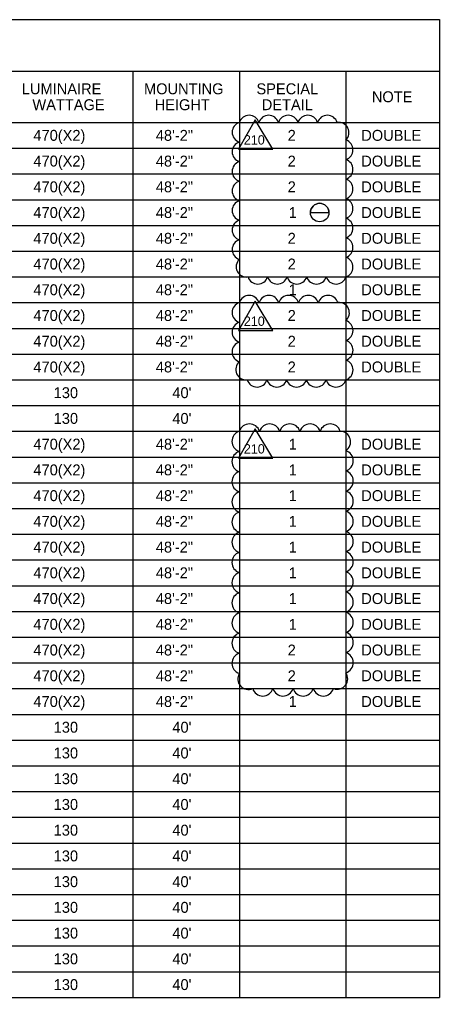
# Model space of a CAD drawing. Extents: x -816.7 to -800.7, y -2197.9 to -2187.9.
# Drawn here: x -811.23 to -808.54, y -2194.13 to -2187.86 of the extents above; entities that cross this region are included whole.
import ezdxf

# ---------------------------------------------------------------- set-up
doc = ezdxf.new("R2010")
doc.units = 0
for name, color, linetype in [('ScratchEle_dp', 7, 'Continuous'), ('SumBoxBorder_dp', 7, 'Continuous'), ('SumBoxLines_dp', 7, 'Continuous'), ('SumBoxLinesMin_dp', 7, 'Continuous'), ('TextLabel', 7, 'Continuous')]:
    doc.layers.add(name, color=color, linetype=linetype)

msp = doc.modelspace()

# ---------------------------------------------------------------- linework, layer by layer
at = {"layer": 'ScratchEle_dp'}
for points in [[(-809.7225, -2188.4998), (-809.8303, -2188.6879), (-809.6096, -2188.6879)], [(-809.7225, -2189.6621), (-809.8303, -2189.8502), (-809.6096, -2189.8502)], [(-809.7225, -2190.4807), (-809.8303, -2190.6688), (-809.6096, -2190.6688)]]:
    msp.add_lwpolyline(points, close=True, dxfattribs=at)
for centre, radius, start, end in [((-809.7621, -2188.536), 0.0657, 17.5, 162.5), ((-809.6368, -2188.536), 0.0657, 17.5, 162.5), ((-809.5114, -2188.536), 0.0657, 17.5, 162.5), ((-809.386, -2188.536), 0.0657, 17.5, 162.5), ((-809.2606, -2188.536), 0.0657, 17.5, 162.5), ((-809.8051, -2188.5789), 0.0657, 107.5, 252.5), ((-809.1878, -2188.5811), 0.0657, 313.82811, 98.82811), ((-809.8051, -2188.7043), 0.0657, 107.5, 252.5), ((-809.1621, -2188.6912), 0.0657, 287.5, 72.5), ((-809.8051, -2188.8297), 0.0657, 107.5, 252.5), ((-809.1621, -2188.8166), 0.0657, 287.5, 72.5), ((-809.8051, -2188.9551), 0.0657, 107.5, 252.5), ((-809.1621, -2188.942), 0.0657, 287.5, 72.5), ((-809.8051, -2189.0804), 0.0657, 107.5, 252.5), ((-809.1621, -2189.0674), 0.0657, 287.5, 72.5), ((-809.8051, -2189.2058), 0.0657, 107.5, 252.5), ((-809.1621, -2189.1927), 0.0657, 287.5, 72.5), ((-809.8051, -2189.3312), 0.0657, 107.5, 252.5), ((-809.1621, -2189.3181), 0.0657, 287.5, 72.5), ((-809.7794, -2189.4413), 0.0657, 133.82811, 278.82811), ((-809.1621, -2189.4435), 0.0657, 287.5, 72.5), ((-809.7066, -2189.4864), 0.0657, 197.5, 342.5), ((-809.5812, -2189.4864), 0.0657, 197.5, 342.5), ((-809.4558, -2189.4864), 0.0657, 197.5, 342.5), ((-809.3304, -2189.4864), 0.0657, 197.5, 342.5), ((-809.205, -2189.4864), 0.0657, 197.5, 342.5), ((-809.8049, -2189.7344), 0.0663, 107.5, 252.5), ((-809.7616, -2189.6911), 0.0663, 17.5, 162.5), ((-809.6352, -2189.6911), 0.0663, 17.5, 162.5), ((-809.5088, -2189.6911), 0.0663, 17.5, 162.5), ((-809.3824, -2189.6911), 0.0663, 17.5, 162.5), ((-809.256, -2189.6911), 0.0663, 17.5, 162.5), ((-809.1858, -2189.737), 0.0662, 311.04336, 96.04336), ((-809.1623, -2189.8502), 0.0663, 287.5, 72.5), ((-809.8049, -2189.8608), 0.0663, 107.5, 252.5), ((-809.1623, -2189.9766), 0.0663, 287.5, 72.5), ((-809.8049, -2189.9872), 0.0663, 107.5, 252.5), ((-809.1623, -2190.103), 0.0663, 287.5, 72.5), ((-809.7814, -2190.1004), 0.0662, 131.04336, 276.04336), ((-809.7112, -2190.1463), 0.0663, 197.5, 342.5), ((-809.5848, -2190.1463), 0.0663, 197.5, 342.5), ((-809.4584, -2190.1463), 0.0663, 197.5, 342.5), ((-809.332, -2190.1463), 0.0663, 197.5, 342.5), ((-809.2055, -2190.1463), 0.0663, 197.5, 342.5), ((-809.7601, -2190.5166), 0.0678, 17.5, 162.5), ((-809.6307, -2190.5166), 0.0678, 17.5, 162.5), ((-809.5013, -2190.5166), 0.0678, 17.5, 162.5), ((-809.3719, -2190.5166), 0.0678, 17.5, 162.5), ((-809.2425, -2190.5166), 0.0678, 17.5, 162.5), ((-809.8044, -2190.5609), 0.0678, 107.5, 252.5), ((-809.1797, -2190.564), 0.0678, 303.41343, 88.41343), ((-809.8044, -2190.6903), 0.0678, 107.5, 252.5), ((-809.1627, -2190.6853), 0.0678, 287.5, 72.5), ((-809.8044, -2190.8197), 0.0678, 107.5, 252.5), ((-809.1627, -2190.8147), 0.0678, 287.5, 72.5), ((-809.8044, -2190.9491), 0.0678, 107.5, 252.5), ((-809.1627, -2190.9441), 0.0678, 287.5, 72.5), ((-809.8044, -2191.0785), 0.0678, 107.5, 252.5), ((-809.1627, -2191.0735), 0.0678, 287.5, 72.5), ((-809.8044, -2191.2079), 0.0678, 107.5, 252.5), ((-809.1627, -2191.2029), 0.0678, 287.5, 72.5), ((-809.8044, -2191.3374), 0.0678, 107.5, 252.5), ((-809.1627, -2191.3323), 0.0678, 287.5, 72.5), ((-809.8044, -2191.4668), 0.0678, 107.5, 252.5), ((-809.1627, -2191.4617), 0.0678, 287.5, 72.5), ((-809.8044, -2191.5962), 0.0678, 107.5, 252.5), ((-809.1627, -2191.5912), 0.0678, 287.5, 72.5), ((-809.8044, -2191.7256), 0.0678, 107.5, 252.5), ((-809.1627, -2191.7206), 0.0678, 287.5, 72.5), ((-809.8044, -2191.855), 0.0678, 107.5, 252.5), ((-809.1627, -2191.85), 0.0678, 287.5, 72.5), ((-809.8044, -2191.9844), 0.0678, 107.5, 252.5), ((-809.1627, -2191.9794), 0.0678, 287.5, 72.5), ((-809.7668, -2192.0842), 0.0678, 148.8508, 293.8508), ((-809.1981, -2192.0826), 0.0678, 249.63724, 34.63724), ((-809.6747, -2192.1258), 0.0678, 197.5, 342.5), ((-809.5453, -2192.1258), 0.0678, 197.5, 342.5), ((-809.4159, -2192.1258), 0.0678, 197.5, 342.5), ((-809.2864, -2192.1258), 0.0678, 197.5, 342.5)]:
    msp.add_arc(centre, radius, start, end, dxfattribs=at)
at = {"layer": 'SumBoxBorder_dp'}
for p, q in [((-815.9673, -2187.8562), (-808.5423, -2187.8562)), ((-808.5423, -2187.8562), (-808.5423, -2194.1262)), ((-808.5423, -2187.8562), (-808.5423, -2194.1262)), ((-815.9673, -2188.1862), (-808.5423, -2188.1862)), ((-815.9673, -2188.1862), (-808.5423, -2188.1862)), ((-815.9673, -2194.1262), (-808.5423, -2194.1262))]:
    msp.add_line(p, q, dxfattribs=at)
at = {"layer": 'SumBoxLines_dp'}
for p, q in [((-810.5073, -2188.1862), (-810.5073, -2194.1262)), ((-810.5073, -2188.1862), (-810.5073, -2194.1262)), ((-809.8248, -2188.1862), (-809.8248, -2194.1262)), ((-809.8248, -2188.1862), (-809.8248, -2192.3112)), ((-809.1423, -2188.1862), (-809.1423, -2194.1262)), ((-815.9673, -2188.5162), (-808.5423, -2188.5162)), ((-809.8248, -2192.4762), (-809.8248, -2194.1262))]:
    msp.add_line(p, q, dxfattribs=at)
at = {"layer": 'SumBoxLinesMin_dp'}
for p, q in [((-815.9673, -2188.5162), (-808.5423, -2188.5162)), ((-815.9673, -2188.6812), (-808.5423, -2188.6812)), ((-815.9673, -2188.6812), (-808.5423, -2188.6812)), ((-815.9673, -2188.8462), (-808.5423, -2188.8462)), ((-815.9673, -2188.8462), (-808.5423, -2188.8462)), ((-815.9673, -2189.0112), (-808.5423, -2189.0112)), ((-815.9673, -2189.0112), (-808.5423, -2189.0112)), ((-815.9673, -2189.1762), (-808.5423, -2189.1762)), ((-815.9673, -2189.1762), (-808.5423, -2189.1762)), ((-815.9673, -2189.3412), (-808.5423, -2189.3412)), ((-815.9673, -2189.3412), (-808.5423, -2189.3412)), ((-815.9673, -2189.5062), (-808.5423, -2189.5062)), ((-815.9673, -2189.5062), (-808.5423, -2189.5062)), ((-815.9673, -2189.6712), (-808.5423, -2189.6712)), ((-815.9673, -2189.6712), (-808.5423, -2189.6712)), ((-815.9673, -2189.8362), (-808.5423, -2189.8362)), ((-815.9673, -2189.8362), (-808.5423, -2189.8362)), ((-815.9673, -2190.0012), (-808.5423, -2190.0012)), ((-815.9673, -2190.0012), (-808.5423, -2190.0012)), ((-815.9673, -2190.1662), (-808.5423, -2190.1662)), ((-815.9673, -2190.1662), (-808.5423, -2190.1662)), ((-815.9673, -2190.3312), (-808.5423, -2190.3312)), ((-815.9673, -2190.3312), (-808.5423, -2190.3312)), ((-815.9673, -2190.4962), (-808.5423, -2190.4962)), ((-815.9673, -2190.4962), (-808.5423, -2190.4962)), ((-815.9673, -2190.6612), (-808.5423, -2190.6612)), ((-815.9673, -2190.6612), (-808.5423, -2190.6612)), ((-815.9673, -2190.8262), (-808.5423, -2190.8262)), ((-815.9673, -2190.8262), (-808.5423, -2190.8262)), ((-815.9673, -2190.9912), (-808.5423, -2190.9912)), ((-815.9673, -2190.9912), (-808.5423, -2190.9912)), ((-815.9673, -2191.1562), (-808.5423, -2191.1562)), ((-815.9673, -2191.1562), (-808.5423, -2191.1562)), ((-815.9673, -2191.3212), (-808.5423, -2191.3212)), ((-815.9673, -2191.3212), (-808.5423, -2191.3212)), ((-815.9673, -2191.4862), (-808.5423, -2191.4862)), ((-815.9673, -2191.4862), (-808.5423, -2191.4862)), ((-815.9673, -2191.6512), (-808.5423, -2191.6512)), ((-815.9673, -2191.6512), (-808.5423, -2191.6512)), ((-815.9673, -2191.8162), (-808.5423, -2191.8162)), ((-815.9673, -2191.8162), (-808.5423, -2191.8162)), ((-815.9673, -2191.9812), (-808.5423, -2191.9812)), ((-815.9673, -2191.9812), (-808.5423, -2191.9812)), ((-815.9673, -2192.1462), (-808.5423, -2192.1462)), ((-815.9673, -2192.1462), (-808.5423, -2192.1462)), ((-815.9673, -2192.3112), (-808.5423, -2192.3112)), ((-815.9673, -2192.3112), (-808.5423, -2192.3112)), ((-815.9673, -2192.4762), (-809.8248, -2192.4762)), ((-815.9673, -2192.4762), (-808.5423, -2192.4762)), ((-809.1423, -2192.4762), (-808.5423, -2192.4762)), ((-815.9673, -2192.6412), (-808.5423, -2192.6412)), ((-815.9673, -2192.6412), (-808.5423, -2192.6412)), ((-815.9673, -2192.8062), (-808.5423, -2192.8062)), ((-815.9673, -2192.8062), (-808.5423, -2192.8062)), ((-815.9673, -2192.9712), (-808.5423, -2192.9712)), ((-815.9673, -2192.9712), (-808.5423, -2192.9712)), ((-815.9673, -2193.1362), (-808.5423, -2193.1362)), ((-815.9673, -2193.1362), (-808.5423, -2193.1362)), ((-815.9673, -2193.3012), (-808.5423, -2193.3012)), ((-815.9673, -2193.3012), (-808.5423, -2193.3012)), ((-815.9673, -2193.4662), (-808.5423, -2193.4662)), ((-815.9673, -2193.4662), (-808.5423, -2193.4662)), ((-815.9673, -2193.6312), (-808.5423, -2193.6312)), ((-815.9673, -2193.6312), (-808.5423, -2193.6312)), ((-815.9673, -2193.7962), (-808.5423, -2193.7962)), ((-815.9673, -2193.7962), (-808.5423, -2193.7962)), ((-815.9673, -2193.9612), (-808.5423, -2193.9612)), ((-815.9673, -2193.9612), (-808.5423, -2193.9612))]:
    msp.add_line(p, q, dxfattribs=at)
at = {"layer": 'TextLabel'}
msp.add_line((-809.3691, -2189.0937), (-809.2505, -2189.0937), dxfattribs=at)
msp.add_line((-809.3691, -2189.0937), (-809.2505, -2189.0937), dxfattribs=at)
msp.add_circle((-809.3098, -2189.0937), 0.0593, dxfattribs=at)
msp.add_arc((-809.3098, -2189.0937), 0.0593, 0, 180, dxfattribs=at)

# ---------------------------------------------------------------- texts
at = {"layer": 'ScratchEle_dp'}
for p in [(-809.7958, -2188.6578), (-809.7958, -2189.8201), (-809.7958, -2190.6387)]:
    msp.add_text('210', height=0.05998, rotation=0, dxfattribs=at).set_placement(p)
at = {"layer": 'TextLabel'}
for s, p in [('LUMINAIRE', (-811.2188, -2188.3352)), ('MOUNTING', (-810.4358, -2188.3352)), ('SPECIAL', (-809.715, -2188.3352)), ('NOTE', (-808.9756, -2188.3862)), ('WATTAGE', (-811.151, -2188.4372)), ('HEIGHT', (-810.3676, -2188.4372)), ('DETAIL', (-809.6811, -2188.4372)), ('470(X2)', (-811.1446, -2188.6337)), ('48\'-2"', (-810.3601, -2188.6337)), ('2', (-809.515, -2188.6337)), ('DOUBLE', (-809.0434, -2188.6337)), ('470(X2)', (-811.1446, -2188.7987)), ('48\'-2"', (-810.3601, -2188.7987)), ('2', (-809.515, -2188.7987)), ('DOUBLE', (-809.0434, -2188.7987)), ('470(X2)', (-811.1446, -2188.9637)), ('48\'-2"', (-810.3601, -2188.9637)), ('2', (-809.515, -2188.9637)), ('DOUBLE', (-809.0434, -2188.9637)), ('470(X2)', (-811.1446, -2189.1287)), ('48\'-2"', (-810.3601, -2189.1287)), ('1', (-809.5083, -2189.1287)), ('DOUBLE', (-809.0434, -2189.1287)), ('470(X2)', (-811.1446, -2189.2937)), ('48\'-2"', (-810.3601, -2189.2937)), ('2', (-809.515, -2189.2937)), ('DOUBLE', (-809.0434, -2189.2937)), ('470(X2)', (-811.1446, -2189.4587)), ('48\'-2"', (-810.3601, -2189.4587)), ('2', (-809.515, -2189.4587)), ('DOUBLE', (-809.0434, -2189.4587)), ('470(X2)', (-811.1446, -2189.6237)), ('48\'-2"', (-810.3601, -2189.6237)), ('1', (-809.5083, -2189.6237)), ('DOUBLE', (-809.0434, -2189.6237)), ('470(X2)', (-811.1446, -2189.7887)), ('48\'-2"', (-810.3601, -2189.7887)), ('2', (-809.515, -2189.7887)), ('DOUBLE', (-809.0434, -2189.7887)), ('470(X2)', (-811.1446, -2189.9537)), ('48\'-2"', (-810.3601, -2189.9537)), ('2', (-809.515, -2189.9537)), ('DOUBLE', (-809.0434, -2189.9537)), ('470(X2)', (-811.1446, -2190.1187)), ('48\'-2"', (-810.3601, -2190.1187)), ('2', (-809.515, -2190.1187)), ('DOUBLE', (-809.0434, -2190.1187)), ('130', (-811.0147, -2190.2837)), ("40'", (-810.254, -2190.2837)), ('130', (-811.0147, -2190.4487)), ("40'", (-810.254, -2190.4487)), ('470(X2)', (-811.1446, -2190.6137)), ('48\'-2"', (-810.3601, -2190.6137)), ('1', (-809.5083, -2190.6137)), ('DOUBLE', (-809.0434, -2190.6137)), ('470(X2)', (-811.1446, -2190.7787)), ('48\'-2"', (-810.3601, -2190.7787)), ('1', (-809.5083, -2190.7787)), ('DOUBLE', (-809.0434, -2190.7787)), ('470(X2)', (-811.1446, -2190.9437)), ('48\'-2"', (-810.3601, -2190.9437)), ('1', (-809.5083, -2190.9437)), ('DOUBLE', (-809.0434, -2190.9437)), ('470(X2)', (-811.1446, -2191.1087)), ('48\'-2"', (-810.3601, -2191.1087)), ('1', (-809.5083, -2191.1087)), ('DOUBLE', (-809.0434, -2191.1087)), ('470(X2)', (-811.1446, -2191.2737)), ('48\'-2"', (-810.3601, -2191.2737)), ('1', (-809.5083, -2191.2737)), ('DOUBLE', (-809.0434, -2191.2737)), ('470(X2)', (-811.1446, -2191.4387)), ('48\'-2"', (-810.3601, -2191.4387)), ('1', (-809.5083, -2191.4387)), ('DOUBLE', (-809.0434, -2191.4387)), ('470(X2)', (-811.1446, -2191.6037)), ('48\'-2"', (-810.3601, -2191.6037)), ('1', (-809.5083, -2191.6037)), ('DOUBLE', (-809.0434, -2191.6037)), ('470(X2)', (-811.1446, -2191.7687)), ('48\'-2"', (-810.3601, -2191.7687)), ('1', (-809.5083, -2191.7687)), ('DOUBLE', (-809.0434, -2191.7687)), ('470(X2)', (-811.1446, -2191.9337)), ('48\'-2"', (-810.3601, -2191.9337)), ('2', (-809.515, -2191.9337)), ('DOUBLE', (-809.0434, -2191.9337)), ('470(X2)', (-811.1446, -2192.0987)), ('48\'-2"', (-810.3601, -2192.0987)), ('2', (-809.515, -2192.0987)), ('DOUBLE', (-809.0434, -2192.0987)), ('470(X2)', (-811.1446, -2192.2637)), ('48\'-2"', (-810.3601, -2192.2637)), ('1', (-809.5083, -2192.2637)), ('DOUBLE', (-809.0434, -2192.2637)), ('130', (-811.0147, -2192.4287)), ("40'", (-810.254, -2192.4287)), ('130', (-811.0147, -2192.5937)), ("40'", (-810.254, -2192.5937)), ('130', (-811.0147, -2192.7587)), ("40'", (-810.254, -2192.7587)), ('130', (-811.0147, -2192.9237)), ("40'", (-810.254, -2192.9237)), ('130', (-811.0147, -2193.0887)), ("40'", (-810.254, -2193.0887)), ('130', (-811.0147, -2193.2537)), ("40'", (-810.254, -2193.2537)), ('130', (-811.0147, -2193.4187)), ("40'", (-810.254, -2193.4187)), ('130', (-811.0147, -2193.5837)), ("40'", (-810.254, -2193.5837)), ('130', (-811.0147, -2193.7487)), ("40'", (-810.254, -2193.7487)), ('130', (-811.0147, -2193.9137)), ("40'", (-810.254, -2193.9137)), ('130', (-811.0147, -2194.0787)), ("40'", (-810.254, -2194.0787))]:
    msp.add_text(s, height=0.07, dxfattribs=at).set_placement(p)

doc.saveas('drawing.dxf')
